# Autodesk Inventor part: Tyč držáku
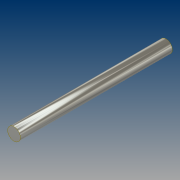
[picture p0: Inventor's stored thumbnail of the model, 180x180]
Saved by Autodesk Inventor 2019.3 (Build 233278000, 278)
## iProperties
Created: 2019-03
Part Number: Tyč držáku
Material: Ocel, měkká, svařovaná
Document SubType Name: Modeling
Designer: B-hon
Density: 7.85 g/cm^3
Appearance: Stříbro
Author: B-hon
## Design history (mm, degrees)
sketch "Náčrt1"
  geometry: C1 r 7.5 at (0, 0); 1 further point
  constraints: 1 centre point, 1 coincident
  dimensions: "d0" = 15 diameter of C1
extrude "Vysunutí1" new body sketch "Náčrt1" distance "d1" = 180; taper "d2" = 0 deg
node "Těleso1"
